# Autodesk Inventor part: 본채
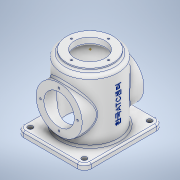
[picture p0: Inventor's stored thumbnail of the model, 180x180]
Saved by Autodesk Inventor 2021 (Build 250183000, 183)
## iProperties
Created: 2021-02
Part Number: 본채
Material: 알루미늄 6061
Document SubType Name: Modeling
Designer: 201-20
Density: 2.7 g/cm^3
Appearance: 알루미늄 - 평지
Mass: 1167.91 g
Surface Area: 1034.28 cm^2
Volume: 432.559 cm^3
Author: 201-20
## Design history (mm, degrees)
sketch "스케치1"
  geometry: L1 (70, 60)-(-70, 60); L2 (-70, 60)-(-70, -60); L3 (-70, -60)-(70, -60); L4 (70, -60)-(70, 60); L5 (70, 60)-(-70, -60); L6 (-70, 60)-(70, -60); 1 further point
  constraints: 12 end point, 3 midpoint, 2 parallel, 1 horizontal, 1 perpendicular
  dimensions: "d1" = 140 distance of L3.end L2.end; "d2" = 120 distance of L2.end L1.end
extrude "돌출1" new body sketch "스케치1" distance "d3" = 10; taper "d4" = 0 deg
sketch "스케치2"
  geometry: C1 r 50 at (0, 0); 1 further point
  constraints: 1 centre point, 1 coincident
  dimensions: "d5" = 100 diameter of C1
extrude "돌출2" join sketch "스케치2" distance "d6" = 120; taper "d7" = 0 deg
sketch "스케치3"
  geometry: 1 further point
fillet "모깎기1" dims "d8" = 12
sketch "스케치4"
  geometry: A1 r 12 centre (-58, 48) between (-58, 60) and (-70, 48) reference; 1 further point
sketch "스케치5"
  geometry: C1 r 42 at (0, 0); 1 further point
  constraints: 1 centre point, 1 coincident
  dimensions: "d9" = 84 diameter of C1
extrude "돌출3" cut sketch "스케치5" distance "d10" = 112; taper "d11" = 0 deg
sketch "스케치6"
  geometry: C1 r 41 at (0, 0); 1 further point
  constraints: 1 centre point, 1 coincident
  dimensions: "d12" = 82 diameter of C1
extrude "돌출4" join sketch "스케치6" distance "d13" = 5; taper "d14" = 0 deg
sketch "스케치7"
  geometry: C1 r 27 at (0, 0); 1 further point
  constraints: 1 centre point, 1 coincident
  dimensions: "d15" = 54 diameter of C1
extrude "돌출5" cut sketch "스케치7" extent not by distance; stored distance "d16" = 5; taper "d17" = 0 deg
sketch "스케치8"
  geometry: A1 r 33 centre (0, 0) between (0, 33) and (-33, 0); 3 further points
  constraints: 4 point on circle, 1 centre point, 1 coincident
  dimensions: "d18" = 66 diameter of A1
node "작업점1"
hole "구멍1" sketch "스케치8" diameter "d19" = 3.242; stored, may be unused: countersink angle "d23" = 90 deg, drill point angle "d25" = 118 deg; dims "d20" = 8, "d21" = 4, "d22" = 2, "d24" = 10
node "작업 평면3"
sketch "스케치10"
  geometry: L1 (0, 48)-(0, -48) reference; L2 (-25, 0)-(150, 0) reference; C1 r 41 at (60, 0); 1 further point
  constraints: 1 centre point, 1 point on line
  dimensions: "d36" = 82 diameter of C1; "d37" = 60 distance from line of L1 C1.centre
extrude "돌출7" join sketch "스케치10" stored distance "d38" = 5; taper "d39" = 0 deg
sketch "스케치11"
  geometry: C1 r 41 at (0, 0) reference; C2 r 27 at (0, 0); 1 further point
  constraints: 1 centre point, 1 coincident
  dimensions: "d40" = 54 diameter of C2
extrude "돌출8" cut sketch "스케치11" extent not by distance; stored distance "d41" = 0; taper "d42" = 0 deg
sketch "스케치12"
  geometry: C1 r 27 at (0, 0) reference; C2 r 41 at (0, 0) reference; A1 r 33 centre (0, 0) between (0, 33) and (-33, 0); 3 further points
  constraints: 4 point on circle, 1 centre point, 1 coincident
  dimensions: "d43" = 66 diameter of A1
hole "구멍2" sketch "스케치12" at (0, 33), (33, 0), (0, -33), (-33, 0) diameter "d44" = 3.242; stored, may be unused: countersink angle "d48" = 90 deg, drill point angle "d50" = 118 deg; dims "d45" = 8, "d46" = 4, "d47" = 2, "d49" = 10
sketch "스케치13"
  geometry: C1 r 41 at (0, 0) reference; C2 r 33 at (0, 0); C3 r 1.621 at (0, 33) reference; C4 r 1.621 at (-33, 0) reference; C5 r 1.621 at (0, -33) reference; C6 r 1.621 at (33, 0) reference; 5 further points
  constraints: 5 coincident, 1 centre point
  dimensions: "d51" = 66 diameter of C2
hole "구멍3" sketch "스케치13" at (0, 33), (33, 0), (0, -33), (-33, 0) diameter "d52" = 3.242; stored, may be unused: countersink angle "d56" = 90 deg, drill point angle "d58" = 118 deg; dims "d53" = 8, "d54" = 4, "d55" = 2, "d57" = 10
fillet "모깎기2" dims "d59" = 3
fillet "모깎기3" dims "d60" = 6
fillet "모깎기4" dims "d61" = 3
fillet "모깎기5" dims "d62" = 3
fillet "모깎기6" dims "d63" = 3
sketch "스케치15"
  geometry: A1 r 12 centre (-58, 48) between (-58, 60) and (-70, 48) reference; A2 r 12 centre (58, 48) between (70, 48) and (58, 60) reference; A3 r 12 centre (58, -48) between (58, -60) and (70, -48) reference; A4 r 12 centre (-58, -48) between (-70, -48) and (-58, -60) reference; 1 further point
hole "구멍4" sketch "스케치15" at (-58, 48), (-58, -48) diameter "d65" = 9; stored, may be unused: countersink angle "d69" = 90 deg, drill point angle "d71" = 118 deg; dims "d66" = 8, "d67" = 4, "d68" = 2, "d70" = 10
sketch "스케치16"
  geometry: A1 r 12 centre (58, 48) between (70, 48) and (58, 60) reference; A2 r 12 centre (58, -48) between (58, -60) and (70, -48) reference; 1 further point
hole "구멍5" sketch "스케치16" at (58, 48), (58, -48) diameter "d72" = 9; stored, may be unused: countersink angle "d76" = 90 deg, drill point angle "d78" = 118 deg; dims "d73" = 8, "d74" = 4, "d75" = 2, "d77" = 10
node "작업 평면4"
sketch "스케치17"
  geometry: 2 further points
  constraints: 1 other
  dimensions: "d80" = 66 vertical distance of point (0.168, 66) point (0, 0)
feature "엠보싱2" sketch "스케치17" dims "d1" = 140, "d2" = 120, "d81" = 0.5, "d82" = 0
fillet "모깎기7" dims "d83" = 3
fillet "모깎기8" dims "d84" = 3
node "솔리드1"
mirror "미러3"
node "투영된 루프1"
node "투영된 루프2"
feature "A9D066F2-1C7D-4E18-AEED-F7BC21143FA4" dims "d65" = 9, "d66" = 8, "d67" = 4, "d68" = 2, "d69" = 90 deg, "d70" = 10, "d71" = 118 deg
other parameters: "d33" = 55, "d79" = -72.5
